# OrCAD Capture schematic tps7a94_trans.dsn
size A; title: TPS7A9401 Transient Model; rev: 1; note: Datasheet: SBVS336C  EVM Guide: SBVU070B
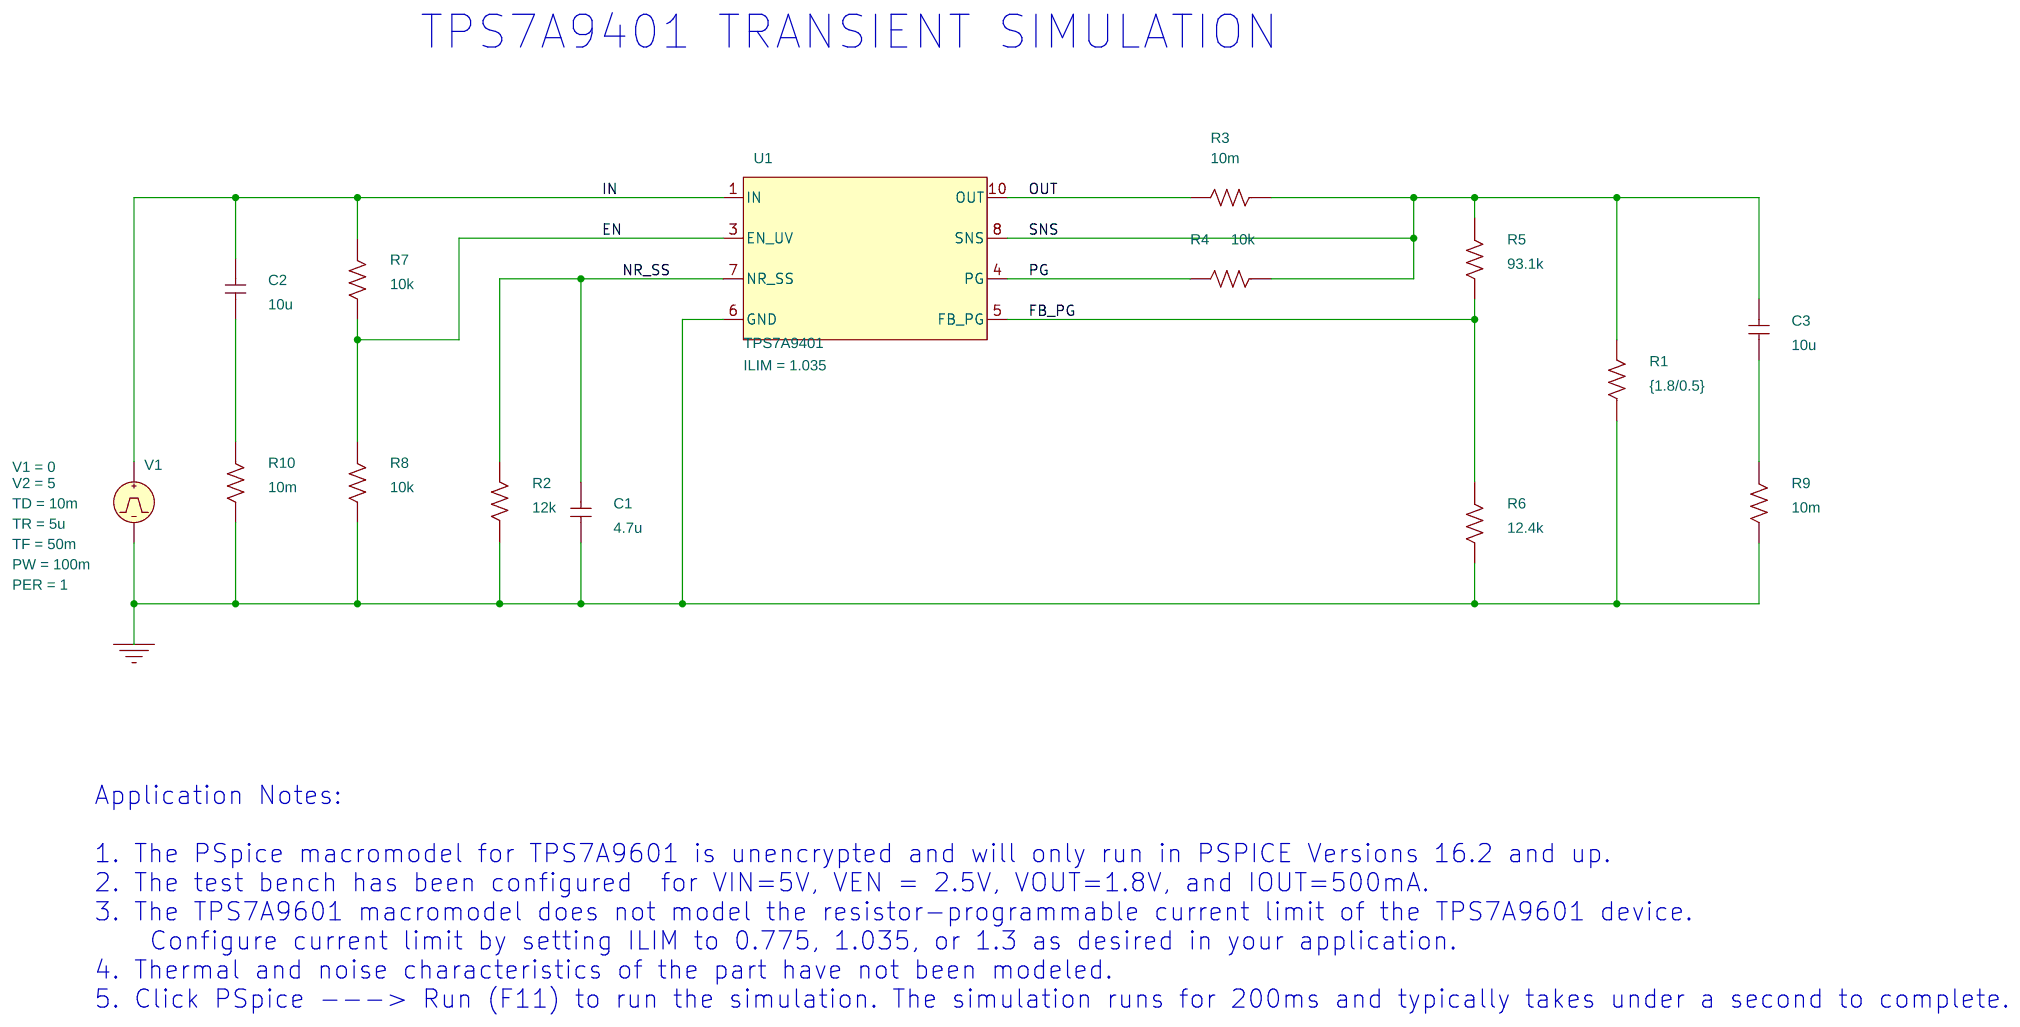
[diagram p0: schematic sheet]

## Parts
C1  4.7u  [RAD/CK05]
C2  10u  [RAD/CK05]
C3  10u  [RAD/CK05]
R1  {1.8/0.5}  [AX/RC05]
R2  12k  [AX/RC05]
R3  10m  [AX/RC05]
R4  10k  [AX/RC05]
R5  93.1k  [AX/RC05]
R6  12.4k  [AX/RC05]
R7  10k  [AX/RC05]
R8  10k  [AX/RC05]
R9  10m  [AX/RC05]
R10  10m  [AX/RC05]
U1  TPS7A9401
V1  VPULSE

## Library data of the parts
C1-C3 = C
R1-R10 = R
U1 = TPS7A9401: ILIM: 1.035
V1 = VPULSE: PER: 1; PW: 100m; TD: 10m; TF: 50m; TR: 5u; V1: 0; V2: 5

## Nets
0: C1.1 R1.1 R2.1 R6.2 R8.2 R9.2 R10.2 U1.6(GND) V1.2(-)
EN: R7.2 R8.1 U1.3(EN_UV)
FB_PG: R5.2 R6.1 U1.5(FB_PG)
IN: C2.2 R7.1 U1.1(IN) V1.1(+)
NR_SS: C1.2 R2.2 U1.7(NR_SS)
OUT: R3.2 U1.10(OUT)
PG: R4.2 U1.4(PG)
SNS: C3.2 R1.2 R3.1 R4.1 R5.1 U1.8(SNS)
N240913: C2.1 R10.1
N241023: C3.1 R9.1

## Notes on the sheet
- TPS7A9401 TRANSIENT SIMULATION
- Application Notes:
  1. The PSpice macromodel for TPS7A9601 is unencrypted and will only run in PSPICE Versions 16.2 and up.
  2. The test bench has been configured  for VIN=5V, VEN = 2.5V, VOUT=1.8V, and IOUT=500mA.
  3. The TPS7A9601 macromodel does not model the resistor-programmable current limit of the TPS7A9601 device.
      Configure current limit by setting ILIM to 0.775, 1.035, or 1.3 as desired in your application.
  4. Thermal and noise characteristics of the part have not been modeled.
  5. Click PSpice ---> Run (F11) to run the simulation. The simulation runs for 200ms and typically takes under a second to complete.
